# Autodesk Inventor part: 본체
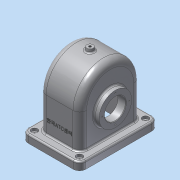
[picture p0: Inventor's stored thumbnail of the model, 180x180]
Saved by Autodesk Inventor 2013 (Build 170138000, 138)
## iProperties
Created: 2016-10
Part Number: 본체
Material: 알루미늄 6061
Document SubType Name: Modeling
Designer: Administrator
Density: 2.71 g/cm^3
Mass: 1165.23 g
Surface Area: 1199.61 cm^2
Volume: 429.976 cm^3
Author: Administrator
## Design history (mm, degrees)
sketch "스케치2"
  geometry: L1 (-43, 75)-(43, 75); L2 (55, 63)-(55, -63); L3 (43, -75)-(-43, -75); L4 (-55, -63)-(-55, 63); A1 r 12 centre (-43, 63) between (-43, 75) and (-55, 63); A2 r 12 centre (43, 63) between (55, 63) and (43, 75); A3 r 12 centre (43, -63) between (43, -75) and (55, -63); A4 r 12 centre (-43, -63) between (-55, -63) and (-43, -75); 6 further points
  constraints: 8 end point, 8 point on circle, 8 tangent, 6 point on line, 4 centre point, 3 equal radius, 2 midpoint, 2 parallel, 1 horizontal, 1 horizontal alignment, 1 perpendicular, 1 vertical alignment
  dimensions: "d0" = 110 distance of point (-55, 75) point (55, 75); "d2" = 150 distance of point (55, 75) point (55, -75); "d3" = 12 radius of A1
extrude "돌출1" new body sketch "스케치2" distance "d4" = 15; taper "d5" = 0 deg
sketch "스케치3"
  geometry: L1 (15, -63)-(15, 63) reference; L2 (80, 58)-(15, 58); L3 (80, -58)-(15, -58); A1 r 58 centre (80, 0) between (80, -58) and (80, 58); 1 further point
  constraints: 4 end point, 2 perpendicular, 2 point on circle, 2 point on line, 2 tangent, 1 centre point, 1 horizontal alignment
  dimensions: "d6" = 116 diameter of A1; "d8" = 80 distance of point (0, 0) A1.centre
extrude "돌출2" join sketch "스케치3" stored distance "d9" = 77; taper "d10" = 0 deg
sketch "스케치4"
  geometry: L1 (15, 58)-(80, 58) reference; L2 (80, -58)-(15, -58) reference; L3 (15, 52)-(80, 52); L4 (80, -52)-(15, -52); L5 (15, 52)-(-29.084, 52); L6 (-29.084, 52)-(-29.084, -52); L7 (-29.084, -52)-(15, -52); A1 r 58 centre (80, 0) between (80, -58) and (80, 58) reference; A2 r 52 centre (80, 0) between (80, -52) and (80, 52); 1 further point
  constraints: 10 end point, 2 parallel, 2 point on circle, 1 centre point, 1 perpendicular, 2 other
  dimensions: "d11" = 6 distance between parallel lines of L1 L3
extrude "돌출3" cut sketch "스케치4" stored distance "d12" = 67; taper "d13" = 0 deg
sketch "스케치7"
  geometry: L1 (-33.5, 132)-(-33.5, 80) reference; L2 (-33.5, 80)-(-33.5, 0) reference; L3 (-74.821, 65)-(72.258, 65); L4 (-43.5, 65)-(-43.5, 102.5); L5 (-43.5, 102.5)-(-33.5, 102.5); L6 (-33.5, 104.747)-(-19.5, 93); L7 (-19.5, 93)-(-19.5, 65); L8 (-38.5, 138)-(-38.5, 80) reference; L9 (-33.5, 102.5)-(-33.5, 104.747); L10 (-43.5, 65)-(-19.5, 65); 1 further point
  constraints: 14 end point, 4 perpendicular, 4 point on line, 2 collinear
  dimensions: "d17" = 65 vertical distance of point (0, 0) L3.end; "d19" = 50 deg angle of L6 L7; "d20" = 24 distance between parallel lines of L4 L7; "d21" = 5 distance between parallel lines of L4 L8; "d22" = 75 diameter of L5 L3; "d23" = 56 diameter of L6.end L3
revolve "회전1" sketch "스케치7" stored, may be unused: angle "d24" = 90 deg
sketch "스케치8"
  geometry: C1 r 31 at (0, 65); 1 further point
  constraints: 1 centre point, 1 vertical alignment
  dimensions: "d25" = 62 diameter of C1; "d27" = 65 distance of point (0, 0) C1.centre
extrude "돌출4" join sketch "스케치8" distance "d28" = 10; taper "d29" = 0 deg
hole "구멍1" diameter "d32" = 40; stored, may be unused: countersink angle "d36" = 90 deg, drill point angle "d38" = 118 deg; dims "d30" = 10, "d31" = 10, "d33" = 6, "d34" = 4, "d35" = 2, "d37" = 8
node "작업 평면1"
sketch "스케치9"
  geometry: C1 r 6 at (0, 0); 1 further point
  constraints: 1 centre point, 1 coincident
  dimensions: "d40" = 12 diameter of C1
extrude "돌출5" join sketch "스케치9" stored distance "d42" = 10; taper "d43" = 10 deg
hole "구멍2" diameter "d46" = 4.459; stored, may be unused: countersink angle "d50" = 90 deg, drill point angle "d52" = 118 deg; dims "d44" = 10, "d45" = 10, "d47" = 30, "d48" = 4, "d49" = 2, "d51" = 30
sketch "스케치10"
  geometry: L1 (13.613, 28.602)-(63.387, 28.602); L2 (63.387, 28.602)-(63.387, 21.398); L3 (63.387, 21.398)-(13.613, 21.398); L4 (13.613, 21.398)-(13.613, 28.602); 4 further points
  constraints: 2 midpoint, 2 vertical alignment, 1 horizontal alignment, 2 other
  dimensions: "d53" = 40 distance of point (38.5, -15) point (38.5, 25)
feature "엠보싱1" sketch "스케치10" dims "d0" = 110, "d2" = 150, "d3" = 12, "d6" = 116, "d8" = 80, "d54" = 0.5, "d55" = 0
sketch "스케치11" dims "d56" = 58
  geometry: C1 r 37.5 at (0, 0) reference; 3 further points
  constraints: 2 vertical alignment, 1 coincident, 2 other
hole "구멍3" sketch "스케치11" at (0, 29) diameter "d58" = 2.459; stored, may be unused: countersink angle "d62" = 90 deg, drill point angle "d64" = 118 deg; dims "d59" = 6, "d60" = 4, "d61" = 2, "d63" = 8
sketch "스케치12" dims "d68" = 52
  geometry: C1 r 31 at (0, 0) reference; 3 further points
  constraints: 2 vertical alignment, 1 coincident, 2 other
hole "구멍4" sketch "스케치12" at (0, 26) diameter "d70" = 2.459; stored, may be unused: countersink angle "d74" = 90 deg, drill point angle "d76" = 118 deg; dims "d71" = 6, "d72" = 4, "d73" = 2, "d75" = 8
sketch "스케치13"
  geometry: A1 r 12 centre (-43, 63) between (-43, 75) and (-55, 63) reference; A2 r 12 centre (43, 63) between (55, 63) and (43, 75) reference; A3 r 12 centre (43, -63) between (43, -75) and (55, -63) reference; A4 r 12 centre (-43, -63) between (-55, -63) and (-43, -75) reference; 1 further point
hole "구멍5" sketch "스케치13" at (-43, -63), (43, -63), (43, 63), (-43, 63) diameter "d80" = 5; stored, may be unused: countersink angle "d84" = 90 deg, drill point angle "d86" = 118 deg; dims "d81" = 6, "d82" = 12, "d83" = 5, "d85" = 8
fillet "모깎기1" dims "d87" = 8
fillet "모깎기2" dims "d88" = 13
fillet "모깎기3" dims "d89" = 3
fillet "모깎기4" dims "d90" = 3
fillet "모깎기5" dims "d91" = 3
fillet "모깎기6" dims "d92" = 3
fillet "모깎기7" dims "d93" = 3
chamfer "모따기1" distance "d94" = 1; stored, may be unused: second distance "d95" = 2, angle "d96" = 45 deg
node "솔리드1"
pattern_circular "원형 패턴1" dims angle "d66" = 360 deg
pattern_circular "원형 패턴2" dims angle "d78" = 360 deg
other parameters: "d39" = 144
